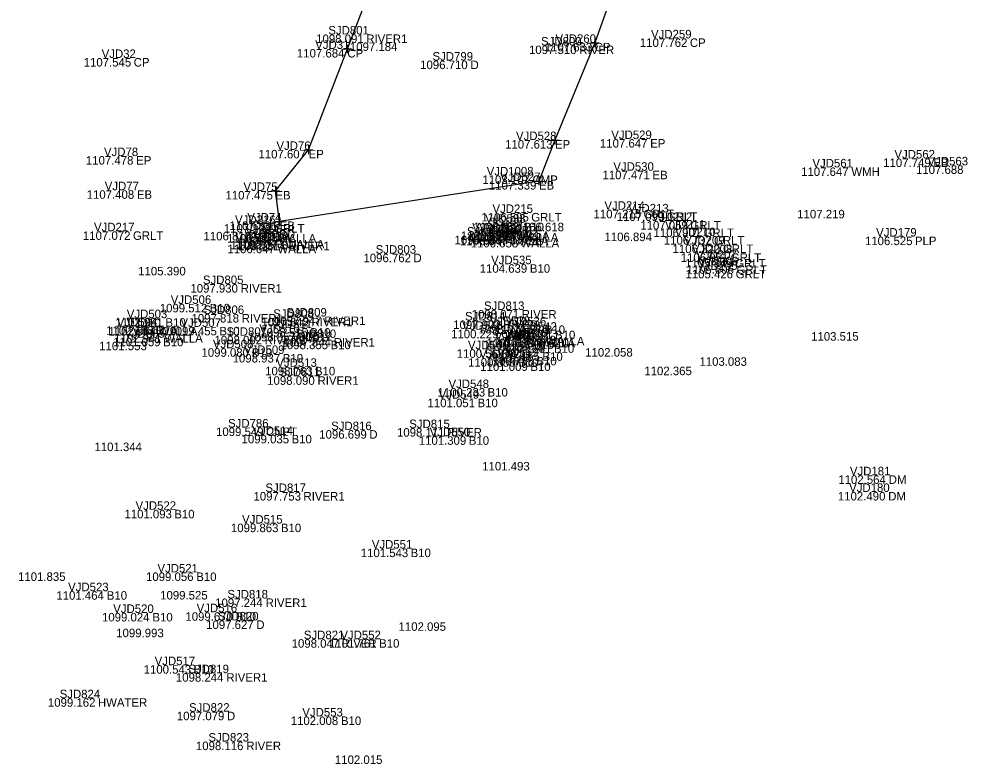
# Model space of a CAD drawing. Extents: x 1629927 to 1630657, y 484405 to 484576.
# Drawn here: x 1630229.8 to 1630340.9, y 484405.3 to 484492.8 of the extents above; entities that cross this region are included whole.
import ezdxf

# ---------------------------------------------------------------- set-up
doc = ezdxf.new("R2010")
doc.units = 0
for name, color, linetype in [('BR_X_SV_Abut_Text', 7, 'Continuous'), ('BR_X_SV_Deck_Top_Text', 7, 'Continuous'), ('PV_X_EOP', 7, 'Continuous'), ('SV_X_Shot_Marker', 7, 'Continuous'), ('SV_X_Text_Comment', 7, 'Continuous'), ('SV_X_Text_Elevation', 7, 'Continuous'), ('SV_X_Text_Name', 7, 'Continuous')]:
    doc.layers.add(name, color=color, linetype=linetype)

msp = doc.modelspace()

# ---------------------------------------------------------------- linework, layer by layer
at = {"layer": 'PV_X_EOP'}
msp.add_lwpolyline([(1630272.75, 484501.05), (1630276.06, 484509.47), (1630305.15, 484510.6), (1630301.74, 484502.19), (1630297.37, 484489.97), (1630292.71, 484478.56), (1630290.83, 484473.75), (1630260.38, 484469.01), (1630259.88, 484472.59), (1630263.78, 484477.41), (1630268.33, 484489.25), (1630272.84, 484501.01)], close=True, dxfattribs=at)
at = {"layer": 'SV_X_Shot_Marker'}
for p, q in [((1630296.87, 484489.97), (1630297.87, 484489.97)), ((1630297.37, 484490.47), (1630297.37, 484489.47)), ((1630297.37, 484489.97), (1630297.37, 484489.97)), ((1630267.83, 484489.25), (1630268.83, 484489.25)), ((1630268.33, 484489.75), (1630268.33, 484488.75)), ((1630268.33, 484489.25), (1630268.33, 484489.25)), ((1630292.71, 484479.06), (1630292.71, 484478.06)), ((1630263.78, 484477.91), (1630263.78, 484476.91)), ((1630292.21, 484478.56), (1630293.21, 484478.56)), ((1630292.71, 484478.56), (1630292.71, 484478.56)), ((1630263.28, 484477.41), (1630264.28, 484477.41)), ((1630263.78, 484477.41), (1630263.78, 484477.41)), ((1630290.33, 484473.75), (1630291.33, 484473.75)), ((1630290.83, 484474.25), (1630290.83, 484473.25)), ((1630290.83, 484473.75), (1630290.83, 484473.75)), ((1630259.38, 484472.59), (1630260.38, 484472.59)), ((1630259.88, 484473.09), (1630259.88, 484472.09)), ((1630259.88, 484472.59), (1630259.88, 484472.59)), ((1630259.88, 484469.01), (1630260.88, 484469.01)), ((1630260.38, 484469.51), (1630260.38, 484468.51)), ((1630260.38, 484469.01), (1630260.38, 484469.01))]:
    msp.add_line(p, q, dxfattribs=at)

# ---------------------------------------------------------------- texts
at = {"layer": 'BR_X_SV_Abut_Text'}
for s, p in [('VJD14', (1630256.33, 484467.53)), ('VJD13', (1630257.34, 484466.85)), ('1106.659', (1630281.66, 484466.84)), ('VJD16', (1630283.63, 484467.21)), ('VJD15', (1630283.79, 484467.84)), ('VJD20', (1630284.78, 484467.65)), ('VJD19', (1630284.91, 484466.96)), ('WALLA', (1630287.55, 484466.84)), ('1106.724', (1630254.22, 484466.53)), ('1106.973', (1630255.23, 484465.85)), ('VJD12', (1630256.38, 484466.28)), ('WALLA', (1630260.14, 484466.53)), ('WALLA', (1630261.09, 484465.85)), ('1106.647', (1630281.53, 484466.21)), ('1106.667', (1630282.68, 484466.65)), ('1106.653', (1630282.81, 484465.96)), ('WALLA', (1630287.42, 484466.21)), ('WALLA', (1630288.58, 484466.65)), ('WALLA', (1630288.67, 484465.96)), ('1106.647', (1630254.24, 484465.28)), ('WALLA', (1630260.13, 484465.28)), ('1102.964', (1630240.28, 484455.62)), ('VJD10', (1630242.41, 484456.62)), ('VJD11', (1630243.05, 484455.8)), ('1102.941', (1630240.94, 484454.8)), ('WALLA', (1630246.2, 484455.62)), ('WALLA', (1630246.82, 484454.8)), ('VJD17', (1630286.76, 484455.25)), ('VJD18', (1630287.84, 484455.47)), ('1101.813', (1630284.67, 484454.25)), ('1101.811', (1630285.75, 484454.47)), ('WALLA', (1630290.53, 484454.25)), ('WALLA', (1630291.63, 484454.47))]:
    msp.add_text(s, height=1, dxfattribs=at).set_placement(p)
at = {"layer": 'BR_X_SV_Deck_Top_Text'}
for s, p in [('JD110', (1630256.55, 484468)), ('JD109', (1630285.04, 484468.47)), ('VJD1003', (1630255.17, 484466.74)), ('0.000', (1630256.81, 484467)), ('BD', (1630260.33, 484467)), ('1106.907', (1630282.44, 484466.84)), ('VJD1002', (1630282.98, 484467.84)), ('0.000', (1630285.27, 484467.47)), ('BD', (1630288.33, 484466.84)), ('BD', (1630288.79, 484467.47)), ('1106.917', (1630254.62, 484465.74)), ('BD', (1630260.51, 484465.74))]:
    msp.add_text(s, height=1, dxfattribs=at).set_placement(p)
at = {"layer": 'SV_X_Text_Comment'}
for s, p in [('RIVER1', (1630270.55, 484489.95)), ('CP', (1630297.37, 484488.97)), ('CP', (1630308.55, 484489.49)), ('CP', (1630268.33, 484488.25)), ('RIVER', (1630295.57, 484488.65)), ('CP', (1630243.24, 484487.19)), ('D', (1630282.79, 484486.89)), ('EP', (1630292.71, 484477.56)), ('EP', (1630303.89, 484477.68)), ('EP', (1630243.53, 484475.68)), ('EP', (1630263.78, 484476.41)), ('EB', (1630337.13, 484475.4)), ('CMP', (1630290.07, 484473.41)), ('EB', (1630304.16, 484473.96)), ('WMH', (1630327.51, 484474.35)), ('EB', (1630290.83, 484472.75)), ('EB', (1630243.62, 484471.67)), ('EB', (1630259.88, 484471.59)), ('GRLT', (1630289.92, 484469.01)), ('GRLT', (1630303.11, 484469.38)), ('GRLT', (1630305.84, 484469.07)), ('EB', (1630260.38, 484468.01)), ('B10', (1630289.04, 484467.86)), ('GRLT', (1630308.61, 484468.06)), ('GRLT', (1630243.15, 484466.85)), ('GRLT', (1630259.73, 484467.71)), ('GRLT', (1630310.16, 484467.18)), ('RIVER', (1630286.81, 484466.34)), ('B10', (1630288.8, 484466.64)), ('GRLT', (1630311.39, 484466.29)), ('PLP', (1630334.98, 484466.23)), ('RIVER1', (1630261.42, 484465.63)), ('GRLT', (1630312.43, 484465.3)), ('D', (1630276.09, 484464.23)), ('GRLT', (1630313.35, 484464.27)), ('GRLT', (1630313.87, 484463.61)), ('B10', (1630289.76, 484462.99)), ('GRLT', (1630313.93, 484462.33)), ('GRLT', (1630314.04, 484462.87)), ('RIVER1', (1630255.81, 484460.66)), ('B10', (1630252.17, 484458.34)), ('RIVER1', (1630255.93, 484457.15)), ('RIVER1', (1630265.62, 484456.85)), ('RIVER', (1630288.81, 484457.62)), ('B10', (1630245.87, 484455.71)), ('B10', (1630246.97, 484456.66)), ('B10', (1630253.3, 484455.64)), ('RIVER1', (1630264.11, 484456.7)), ('RIVER', (1630286.63, 484456.39)), ('B10', (1630289.6, 484455.87)), ('B10', (1630291.51, 484455.81)), ('RIVER1', (1630258.61, 484454.59)), ('B10', (1630262.59, 484454.94)), ('B10', (1630263.98, 484455.49)), ('CMP', (1630286.39, 484455.3)), ('B10', (1630292.72, 484455.19)), ('B10', (1630246.7, 484454.36)), ('B10', (1630266.36, 484454.02)), ('RIVER1', (1630266.74, 484454.33)), ('B10', (1630290.2, 484454.03)), ('B10', (1630291.96, 484454.25)), ('B10', (1630292.59, 484453.6)), ('B10', (1630257.12, 484453.13)), ('B10', (1630260.75, 484452.46)), ('FDO', (1630287.06, 484453.01)), ('B10', (1630291.24, 484452.66)), ('B10', (1630288.4, 484451.96)), ('B10', (1630289.82, 484451.47)), ('B10', (1630290.53, 484452.12)), ('B10', (1630264.53, 484450.95)), ('RIVER1', (1630264.83, 484449.84)), ('B10', (1630284.79, 484448.46)), ('B10', (1630283.62, 484447.21)), ('CNPT', (1630258.79, 484443.83)), ('D', (1630270.91, 484443.52)), ('RIVER', (1630280.04, 484443.76)), ('B10', (1630261.78, 484442.97)), ('B10', (1630282.59, 484442.8)), ('DM', (1630331.9, 484438.22)), ('RIVER1', (1630263.18, 484436.26)), ('DM', (1630331.84, 484436.27)), ('B10', (1630248.01, 484434.17)), ('B10', (1630260.53, 484432.55)), ('B10', (1630275.76, 484429.62)), ('B10', (1630250.59, 484426.82)), ('B10', (1630240.08, 484424.62)), ('RIVER1', (1630258.73, 484423.77)), ('B10', (1630245.44, 484422.07)), ('B10', (1630255.22, 484422.15)), ('D', (1630257.64, 484421.19)), ('RIVER', (1630267.68, 484418.99)), ('B10', (1630272.06, 484418.99)), ('B10', (1630250.27, 484415.94)), ('RIVER1', (1630254.12, 484415)), ('HWATER', (1630239.04, 484412.06)), ('D', (1630254.19, 484410.48)), ('B10', (1630267.58, 484409.92)), ('RIVER', (1630256.46, 484406.97))]:
    msp.add_text(s, height=1, dxfattribs=at).set_placement(p)
at = {"layer": 'SV_X_Text_Elevation'}
for s, p in [('1098.091', (1630264.67, 484489.95)), ('1097.184', (1630268.63, 484489.01)), ('1107.633', (1630291.5, 484488.97)), ('1107.762', (1630302.68, 484489.49)), ('1107.684', (1630262.41, 484488.25)), ('1097.510', (1630289.66, 484488.65)), ('1107.545', (1630237.37, 484487.19)), ('1096.710', (1630276.88, 484486.89)), ('1107.613', (1630286.85, 484477.56)), ('1107.647', (1630297.99, 484477.68)), ('1107.478', (1630237.63, 484475.68)), ('1107.607', (1630257.89, 484476.41)), ('1107.749', (1630331.25, 484475.4)), ('1107.688', (1630335.1, 484474.59)), ('1103.107', (1630284.18, 484473.41)), ('1107.471', (1630298.28, 484473.96)), ('1107.647', (1630321.61, 484474.35)), ('1107.339', (1630284.95, 484472.75)), ('1107.408', (1630237.72, 484471.67)), ('1107.475', (1630254.02, 484471.59)), ('1106.595', (1630284.06, 484469.01)), ('1107.215', (1630297.24, 484469.38)), ('1107.099', (1630299.96, 484469.07)), ('1107.219', (1630321.16, 484469.37)), ('1107.336', (1630254.48, 484468.01)), ('1105.974', (1630283.12, 484467.86)), ('1106.618', (1630288.19, 484467.86)), ('1107.059', (1630302.73, 484468.06)), ('1107.072', (1630237.28, 484466.85)), ('1106.816', (1630251.44, 484466.79)), ('1107.138', (1630253.83, 484467.71)), ('1106.901', (1630304.29, 484467.18)), ('1097.314', (1630255.5, 484465.63)), ('1096.838', (1630280.92, 484466.34)), ('1105.595', (1630282.94, 484466.64)), ('1106.894', (1630298.52, 484466.7)), ('1106.737', (1630305.49, 484466.29)), ('1106.525', (1630329.11, 484466.23)), ('1106.320', (1630306.52, 484465.3)), ('1096.762', (1630270.22, 484464.23)), ('1106.051', (1630307.47, 484464.27)), ('1105.849', (1630307.99, 484463.61)), ('1105.390', (1630243.77, 484462.68)), ('1104.639', (1630283.87, 484462.99)), ('1105.426', (1630308.03, 484462.33)), ('1105.606', (1630308.14, 484462.87)), ('1097.930', (1630249.9, 484460.66)), ('1099.512', (1630246.3, 484458.34)), ('1097.818', (1630250.03, 484457.15)), ('1097.947', (1630259.72, 484456.85)), ('1098.071', (1630282.93, 484457.62)), ('1102.133', (1630240, 484455.71)), ('1102.981', (1630241.09, 484456.66)), ('1099.455', (1630247.43, 484455.64)), ('1097.642', (1630258.23, 484456.7)), ('1097.902', (1630280.76, 484456.39)), ('1098.971', (1630283.72, 484455.87)), ('1101.927', (1630285.61, 484455.81)), ('1098.002', (1630252.73, 484454.59)), ('1098.857', (1630256.7, 484454.94)), ('1098.515', (1630258.11, 484455.49)), ('1100.229', (1630280.51, 484455.3)), ('1101.891', (1630286.84, 484455.19)), ('1103.515', (1630322.79, 484455.02)), ('1101.553', (1630239.2, 484453.9)), ('1101.059', (1630240.82, 484454.36)), ('1098.355', (1630260.49, 484454.02)), ('1097.844', (1630260.82, 484454.33)), ('1100.141', (1630284.32, 484454.03)), ('1101.048', (1630286.06, 484454.25)), ('1101.381', (1630286.71, 484453.6)), ('1099.080', (1630251.2, 484453.13)), ('1098.937', (1630254.86, 484452.46)), ('1100.569', (1630281.17, 484453.01)), ('1101.155', (1630285.37, 484452.66)), ('1102.058', (1630296.26, 484453.15)), ('1100.856', (1630282.5, 484451.96)), ('1101.009', (1630283.94, 484451.47)), ('1100.785', (1630284.66, 484452.12)), ('1103.083', (1630309.67, 484452.07)), ('1098.763', (1630258.67, 484450.95)), ('1102.365', (1630303.2, 484450.97)), ('1098.090', (1630258.92, 484449.84)), ('1100.233', (1630278.93, 484448.46)), ('1101.051', (1630277.74, 484447.21)), ('1099.549', (1630252.91, 484443.83)), ('1096.699', (1630265.03, 484443.52)), ('1098.111', (1630274.16, 484443.76)), ('1099.035', (1630255.91, 484442.97)), ('1101.309', (1630276.71, 484442.8)), ('1101.344', (1630238.63, 484442.06)), ('1101.493', (1630284.17, 484439.79)), ('1102.564', (1630325.98, 484438.22)), ('1097.753', (1630257.31, 484436.26)), ('1102.490', (1630325.93, 484436.27)), ('1101.093', (1630242.15, 484434.17)), ('1099.863', (1630254.66, 484432.55)), ('1101.543', (1630269.9, 484429.62)), ('1101.835', (1630229.66, 484426.83)), ('1099.056', (1630244.69, 484426.82)), ('1101.464', (1630234.16, 484424.62)), ('1099.525', (1630246.35, 484424.65)), ('1097.244', (1630252.81, 484423.77)), ('1099.024', (1630239.52, 484422.07)), ('1099.670', (1630249.31, 484422.15)), ('1097.627', (1630251.75, 484421.19)), ('1099.993', (1630241.19, 484420.22)), ('1102.095', (1630274.34, 484420.97)), ('1098.047', (1630261.79, 484418.99)), ('1101.761', (1630266.18, 484418.99)), ('1100.543', (1630244.41, 484415.94)), ('1098.244', (1630248.2, 484415)), ('1099.162', (1630233.17, 484412.06)), ('1097.079', (1630248.31, 484410.48)), ('1102.008', (1630261.68, 484409.92)), ('1098.116', (1630250.55, 484406.97)), ('1102.015', (1630266.87, 484405.35))]:
    msp.add_text(s, height=1, dxfattribs=at).set_placement(p)
at = {"layer": 'SV_X_Text_Name'}
for s, p in [('SJD801', (1630266.1, 484490.95)), ('VJD259', (1630303.99, 484490.49)), ('VJD31', (1630264.56, 484489.25)), ('SJD800', (1630291.08, 484489.65)), ('VJD260', (1630292.77, 484489.97)), ('VJD32', (1630239.48, 484488.19)), ('SJD799', (1630278.33, 484487.89)), ('VJD528', (1630288.13, 484478.56)), ('VJD529', (1630299.32, 484478.68)), ('VJD76', (1630260, 484477.41)), ('VJD78', (1630239.75, 484476.68)), ('VJD562', (1630332.57, 484476.4)), ('VJD530', (1630299.56, 484474.96)), ('VJD561', (1630322.94, 484475.35)), ('VJD563', (1630336.46, 484475.59)), ('VJD1008', (1630284.69, 484474.41)), ('VJD527', (1630286.25, 484473.75)), ('VJD77', (1630239.84, 484472.67)), ('VJD75', (1630256.13, 484472.59)), ('VJD214', (1630298.51, 484470.38)), ('VJD213', (1630301.3, 484470.07)), ('VJD74', (1630256.58, 484469.01)), ('VJD215', (1630285.37, 484470.01)), ('VJD212', (1630304.06, 484469.06)), ('VJD217', (1630238.58, 484467.85)), ('VJD216', (1630255.14, 484468.71)), ('VJD533', (1630284.5, 484468.86)), ('VJD211', (1630305.6, 484468.18)), ('SJD812', (1630282.37, 484467.34)), ('VJD534', (1630284.2, 484467.64)), ('VJD210', (1630306.79, 484467.29)), ('VJD179', (1630330.42, 484467.23)), ('SJD804', (1630256.93, 484466.63)), ('VJD209', (1630307.87, 484466.3)), ('SJD803', (1630271.65, 484465.23)), ('VJD208', (1630308.77, 484465.27)), ('VJD207', (1630309.3, 484464.61)), ('VJD535', (1630285.21, 484463.99)), ('VJD206', (1630309.46, 484463.87)), ('VJD205', (1630309.38, 484463.33)), ('SJD805', (1630251.37, 484461.66)), ('VJD506', (1630247.59, 484459.34)), ('SJD806', (1630251.45, 484458.15)), ('SJD809', (1630261.16, 484457.85)), ('SJD813', (1630284.37, 484458.62)), ('VJD503', (1630242.43, 484457.66)), ('SJD808', (1630259.63, 484457.7)), ('SJD814', (1630282.14, 484457.39)), ('VJD539', (1630285.04, 484456.87)), ('VJD536', (1630286.92, 484456.81)), ('VJD504', (1630241.26, 484456.71)), ('VJD507', (1630248.73, 484456.64)), ('VJD510', (1630258, 484455.94)), ('VJD511', (1630259.42, 484456.49)), ('VJD540', (1630281.8, 484456.3)), ('VJD542', (1630288.17, 484456.19)), ('VJD505', (1630242.15, 484455.36)), ('SJD807', (1630254.14, 484455.59)), ('VJD512', (1630261.81, 484455.02)), ('SJD810', (1630262.25, 484455.33)), ('VJD538', (1630285.62, 484455.03)), ('VJD537', (1630287.38, 484455.25)), ('VJD543', (1630288.05, 484454.6)), ('VJD508', (1630252.54, 484454.13)), ('VJD509', (1630256.19, 484453.46)), ('VJD541', (1630282.49, 484454.01)), ('VJD544', (1630286.64, 484453.66)), ('VJD547', (1630283.82, 484452.96)), ('VJD546', (1630285.23, 484452.47)), ('VJD545', (1630285.98, 484453.12)), ('VJD513', (1630259.99, 484451.95)), ('SJD811', (1630260.37, 484450.84)), ('VJD548', (1630280.21, 484449.46)), ('VJD549', (1630279.05, 484448.21)), ('SJD786', (1630254.32, 484444.83)), ('SJD816', (1630266.43, 484444.52)), ('SJD815', (1630275.6, 484444.76)), ('VJD514', (1630257.18, 484443.97)), ('VJD550', (1630278, 484443.8)), ('VJD181', (1630327.34, 484439.22)), ('SJD817', (1630258.71, 484437.26)), ('VJD180', (1630327.25, 484437.27)), ('VJD522', (1630243.46, 484435.17)), ('VJD515', (1630255.97, 484433.55)), ('VJD551', (1630271.2, 484430.62)), ('VJD521', (1630246.03, 484427.82)), ('VJD523', (1630235.54, 484425.62)), ('SJD818', (1630254.25, 484424.77)), ('VJD520', (1630240.84, 484423.07)), ('VJD516', (1630250.63, 484423.15)), ('SJD820', (1630253.15, 484422.19)), ('SJD821', (1630263.22, 484419.99)), ('VJD552', (1630267.51, 484419.99)), ('VJD517', (1630245.7, 484416.94)), ('SJD819', (1630249.67, 484416)), ('SJD824', (1630234.55, 484413.06)), ('SJD822', (1630249.74, 484411.48)), ('VJD553', (1630263.04, 484410.92)), ('SJD823', (1630252.02, 484407.97))]:
    msp.add_text(s, height=1, dxfattribs=at).set_placement(p)

doc.saveas('drawing.dxf')
